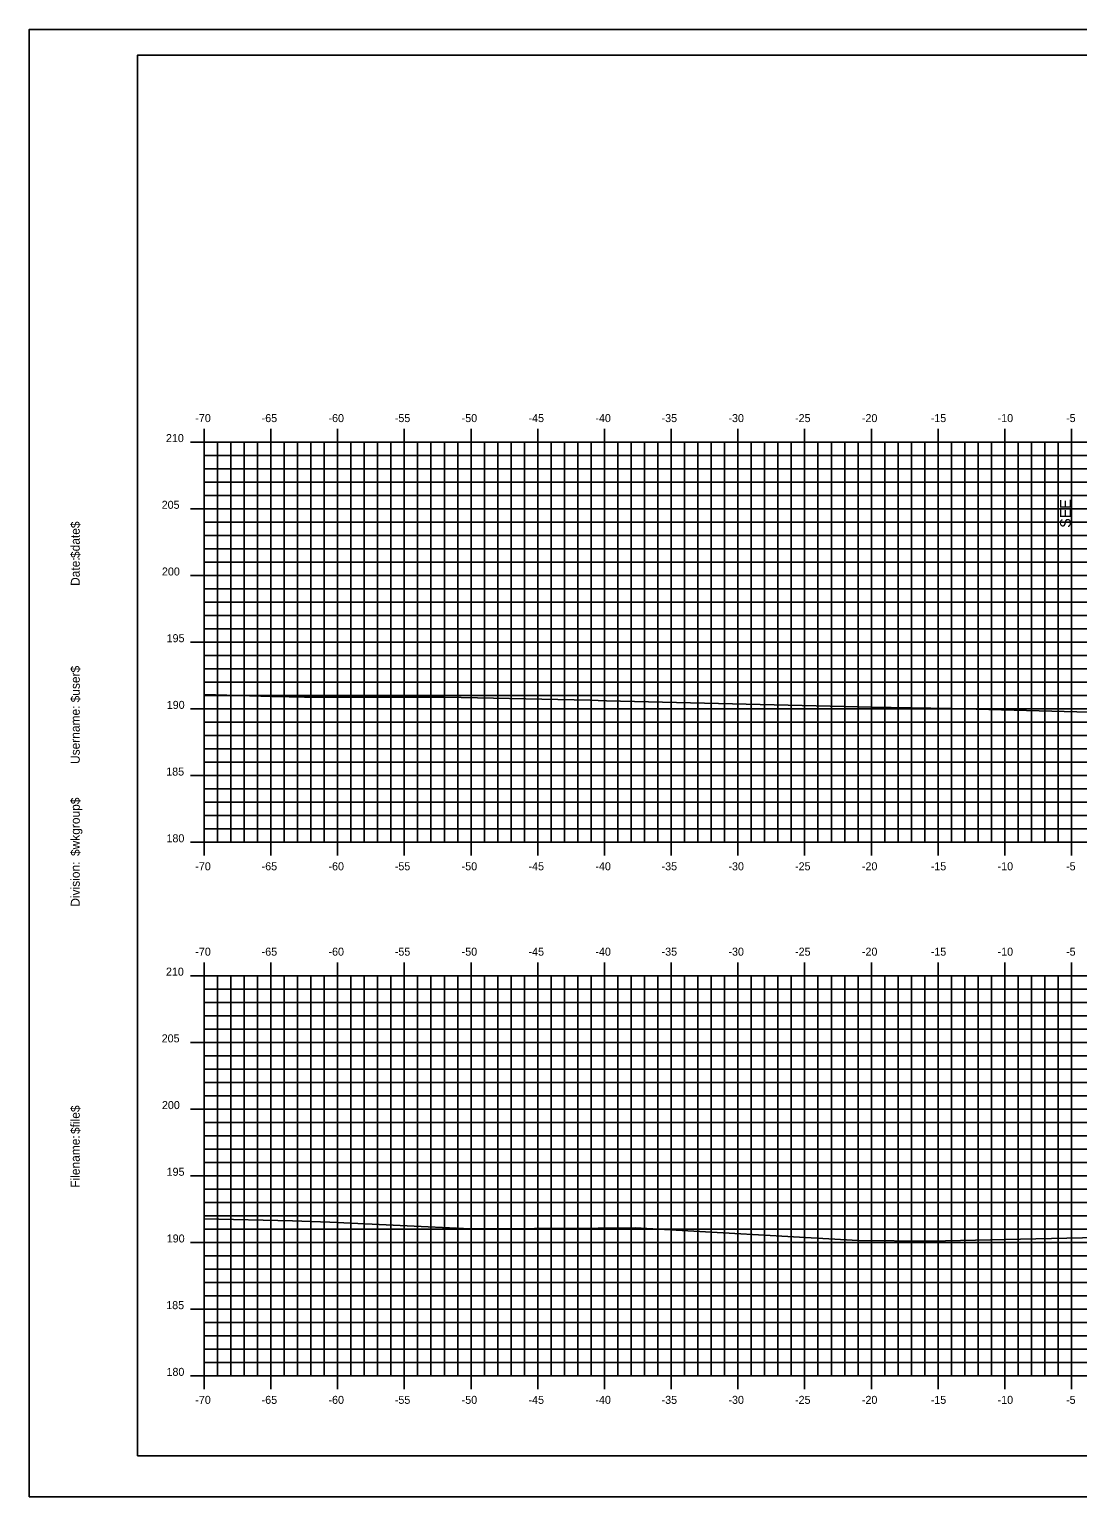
# Model space of a CAD drawing. Extents: x 1723074 to 1723246, y 459560 to 459670.
# Drawn here: x 1723074.4 to 1723152.9, y 459559.6 to 459669.6 of the extents above; entities that cross this region are included whole.
import ezdxf

# ---------------------------------------------------------------- set-up
doc = ezdxf.new("R2010")
doc.units = 0
for name, color, linetype in [('ANNOTATION', 7, 'Continuous'), ('BORDER', 7, 'Continuous'), ('H_V ANNOTATION', 7, 'Continuous'), ('MAJOR', 7, 'Continuous'), ('MINOR', 7, 'Continuous'), ('PLOT BOUNDARY', 7, 'Continuous'), ('S_Roadway_Centerline', 7, 'Continuous')]:
    doc.layers.add(name, color=color, linetype=linetype)

msp = doc.modelspace()

# ---------------------------------------------------------------- linework, layer by layer
at = {"layer": 'BORDER'}
msp.add_lwpolyline([(1723082.45, 459562.61), (1723242.45, 459562.61), (1723242.45, 459667.61), (1723082.45, 459667.61)], close=True, dxfattribs=at)
at = {"layer": 'MAJOR'}
for p, q in [((1723087.45, 459639.61), (1723087.45, 459638.61)), ((1723092.45, 459639.61), (1723092.45, 459638.61)), ((1723097.45, 459639.61), (1723097.45, 459638.61)), ((1723102.45, 459639.61), (1723102.45, 459638.61)), ((1723107.45, 459639.61), (1723107.45, 459638.61)), ((1723112.45, 459639.61), (1723112.45, 459638.61)), ((1723117.45, 459639.61), (1723117.45, 459638.61)), ((1723122.45, 459639.61), (1723122.45, 459638.61)), ((1723127.45, 459639.61), (1723127.45, 459638.61)), ((1723132.45, 459639.61), (1723132.45, 459638.61)), ((1723137.45, 459639.61), (1723137.45, 459638.61)), ((1723142.45, 459639.61), (1723142.45, 459638.61)), ((1723147.45, 459639.61), (1723147.45, 459638.61)), ((1723152.45, 459639.61), (1723152.45, 459638.61)), ((1723086.44, 459638.61), (1723087.45, 459638.61)), ((1723087.45, 459638.61), (1723227.45, 459638.61)), ((1723087.45, 459608.61), (1723087.45, 459638.61)), ((1723087.45, 459608.61), (1723087.45, 459638.61)), ((1723087.45, 459638.61), (1723227.45, 459638.61)), ((1723092.45, 459608.61), (1723092.45, 459638.61)), ((1723097.45, 459608.61), (1723097.45, 459638.61)), ((1723102.45, 459608.61), (1723102.45, 459638.61)), ((1723107.45, 459608.61), (1723107.45, 459638.61)), ((1723112.45, 459608.61), (1723112.45, 459638.61)), ((1723117.45, 459608.61), (1723117.45, 459638.61)), ((1723122.45, 459608.61), (1723122.45, 459638.61)), ((1723127.45, 459608.61), (1723127.45, 459638.61)), ((1723132.45, 459608.61), (1723132.45, 459638.61)), ((1723137.45, 459608.61), (1723137.45, 459638.61)), ((1723142.45, 459608.61), (1723142.45, 459638.61)), ((1723147.45, 459608.61), (1723147.45, 459638.61)), ((1723152.45, 459608.61), (1723152.45, 459638.61)), ((1723086.44, 459633.61), (1723087.45, 459633.61)), ((1723087.45, 459633.61), (1723227.45, 459633.61)), ((1723086.44, 459628.61), (1723087.45, 459628.61)), ((1723087.45, 459628.61), (1723227.45, 459628.61)), ((1723086.44, 459623.61), (1723087.45, 459623.61)), ((1723087.45, 459623.61), (1723227.45, 459623.61)), ((1723086.44, 459618.61), (1723087.45, 459618.61)), ((1723087.45, 459618.61), (1723227.45, 459618.61)), ((1723086.44, 459613.61), (1723087.45, 459613.61)), ((1723087.45, 459613.61), (1723227.45, 459613.61)), ((1723086.44, 459608.61), (1723087.45, 459608.61)), ((1723087.45, 459608.61), (1723227.45, 459608.61)), ((1723087.45, 459608.61), (1723227.45, 459608.61)), ((1723087.45, 459607.61), (1723087.45, 459608.61)), ((1723092.45, 459607.61), (1723092.45, 459608.61)), ((1723097.45, 459607.61), (1723097.45, 459608.61)), ((1723102.45, 459607.61), (1723102.45, 459608.61)), ((1723107.45, 459607.61), (1723107.45, 459608.61)), ((1723112.45, 459607.61), (1723112.45, 459608.61)), ((1723117.45, 459607.61), (1723117.45, 459608.61)), ((1723122.45, 459607.61), (1723122.45, 459608.61)), ((1723127.45, 459607.61), (1723127.45, 459608.61)), ((1723132.45, 459607.61), (1723132.45, 459608.61)), ((1723137.45, 459607.61), (1723137.45, 459608.61)), ((1723142.45, 459607.61), (1723142.45, 459608.61)), ((1723147.45, 459607.61), (1723147.45, 459608.61)), ((1723152.45, 459607.61), (1723152.45, 459608.61)), ((1723087.45, 459599.61), (1723087.45, 459598.61)), ((1723092.45, 459599.61), (1723092.45, 459598.61)), ((1723097.45, 459599.61), (1723097.45, 459598.61)), ((1723102.45, 459599.61), (1723102.45, 459598.61)), ((1723107.45, 459599.61), (1723107.45, 459598.61)), ((1723112.45, 459599.61), (1723112.45, 459598.61)), ((1723117.45, 459599.61), (1723117.45, 459598.61)), ((1723122.45, 459599.61), (1723122.45, 459598.61)), ((1723127.45, 459599.61), (1723127.45, 459598.61)), ((1723132.45, 459599.61), (1723132.45, 459598.61)), ((1723137.45, 459599.61), (1723137.45, 459598.61)), ((1723142.45, 459599.61), (1723142.45, 459598.61)), ((1723147.45, 459599.61), (1723147.45, 459598.61)), ((1723152.45, 459599.61), (1723152.45, 459598.61)), ((1723086.44, 459598.61), (1723087.45, 459598.61)), ((1723087.45, 459598.61), (1723227.45, 459598.61)), ((1723087.45, 459568.61), (1723087.45, 459598.61)), ((1723087.45, 459568.61), (1723087.45, 459598.61)), ((1723087.45, 459598.61), (1723227.45, 459598.61)), ((1723092.45, 459568.61), (1723092.45, 459598.61)), ((1723097.45, 459568.61), (1723097.45, 459598.61)), ((1723102.45, 459568.61), (1723102.45, 459598.61)), ((1723107.45, 459568.61), (1723107.45, 459598.61)), ((1723112.45, 459568.61), (1723112.45, 459598.61)), ((1723117.45, 459568.61), (1723117.45, 459598.61)), ((1723122.45, 459568.61), (1723122.45, 459598.61)), ((1723127.45, 459568.61), (1723127.45, 459598.61)), ((1723132.45, 459568.61), (1723132.45, 459598.61)), ((1723137.45, 459568.61), (1723137.45, 459598.61)), ((1723142.45, 459568.61), (1723142.45, 459598.61)), ((1723147.45, 459568.61), (1723147.45, 459598.61)), ((1723152.45, 459568.61), (1723152.45, 459598.61)), ((1723086.44, 459593.61), (1723087.45, 459593.61)), ((1723087.45, 459593.61), (1723227.45, 459593.61)), ((1723086.44, 459588.61), (1723087.45, 459588.61)), ((1723087.45, 459588.61), (1723227.45, 459588.61)), ((1723086.44, 459583.61), (1723087.45, 459583.61)), ((1723087.45, 459583.61), (1723227.45, 459583.61)), ((1723086.44, 459578.61), (1723087.45, 459578.61)), ((1723087.45, 459578.61), (1723227.45, 459578.61)), ((1723086.44, 459573.61), (1723087.45, 459573.61)), ((1723087.45, 459573.61), (1723227.45, 459573.61)), ((1723086.44, 459568.61), (1723087.45, 459568.61)), ((1723087.45, 459568.61), (1723227.45, 459568.61)), ((1723087.45, 459568.61), (1723227.45, 459568.61)), ((1723087.45, 459567.61), (1723087.45, 459568.61)), ((1723092.45, 459567.61), (1723092.45, 459568.61)), ((1723097.45, 459567.61), (1723097.45, 459568.61)), ((1723102.45, 459567.61), (1723102.45, 459568.61)), ((1723107.45, 459567.61), (1723107.45, 459568.61)), ((1723112.45, 459567.61), (1723112.45, 459568.61)), ((1723117.45, 459567.61), (1723117.45, 459568.61)), ((1723122.45, 459567.61), (1723122.45, 459568.61)), ((1723127.45, 459567.61), (1723127.45, 459568.61)), ((1723132.45, 459567.61), (1723132.45, 459568.61)), ((1723137.45, 459567.61), (1723137.45, 459568.61)), ((1723142.45, 459567.61), (1723142.45, 459568.61)), ((1723147.45, 459567.61), (1723147.45, 459568.61)), ((1723152.45, 459567.61), (1723152.45, 459568.61))]:
    msp.add_line(p, q, dxfattribs=at)
at = {"layer": 'MINOR'}
for p, q in [((1723088.45, 459608.61), (1723088.45, 459638.61)), ((1723089.45, 459608.61), (1723089.45, 459638.61)), ((1723090.45, 459608.61), (1723090.45, 459638.61)), ((1723091.45, 459608.61), (1723091.45, 459638.61)), ((1723093.45, 459608.61), (1723093.45, 459638.61)), ((1723094.45, 459608.61), (1723094.45, 459638.61)), ((1723095.45, 459608.61), (1723095.45, 459638.61)), ((1723096.45, 459608.61), (1723096.45, 459638.61)), ((1723098.45, 459608.61), (1723098.45, 459638.61)), ((1723099.45, 459608.61), (1723099.45, 459638.61)), ((1723100.45, 459608.61), (1723100.45, 459638.61)), ((1723101.45, 459608.61), (1723101.45, 459638.61)), ((1723103.45, 459608.61), (1723103.45, 459638.61)), ((1723104.45, 459608.61), (1723104.45, 459638.61)), ((1723105.45, 459608.61), (1723105.45, 459638.61)), ((1723106.45, 459608.61), (1723106.45, 459638.61)), ((1723108.45, 459608.61), (1723108.45, 459638.61)), ((1723109.45, 459608.61), (1723109.45, 459638.61)), ((1723110.45, 459608.61), (1723110.45, 459638.61)), ((1723111.45, 459608.61), (1723111.45, 459638.61)), ((1723113.45, 459608.61), (1723113.45, 459638.61)), ((1723114.45, 459608.61), (1723114.45, 459638.61)), ((1723115.45, 459608.61), (1723115.45, 459638.61)), ((1723116.45, 459608.61), (1723116.45, 459638.61)), ((1723118.45, 459608.61), (1723118.45, 459638.61)), ((1723119.45, 459608.61), (1723119.45, 459638.61)), ((1723120.45, 459608.61), (1723120.45, 459638.61)), ((1723121.45, 459608.61), (1723121.45, 459638.61)), ((1723123.45, 459608.61), (1723123.45, 459638.61)), ((1723124.45, 459608.61), (1723124.45, 459638.61)), ((1723125.45, 459608.61), (1723125.45, 459638.61)), ((1723126.45, 459608.61), (1723126.45, 459638.61)), ((1723128.45, 459608.61), (1723128.45, 459638.61)), ((1723129.45, 459608.61), (1723129.45, 459638.61)), ((1723130.45, 459608.61), (1723130.45, 459638.61)), ((1723131.45, 459608.61), (1723131.45, 459638.61)), ((1723133.45, 459608.61), (1723133.45, 459638.61)), ((1723134.45, 459608.61), (1723134.45, 459638.61)), ((1723135.45, 459608.61), (1723135.45, 459638.61)), ((1723136.45, 459608.61), (1723136.45, 459638.61)), ((1723138.45, 459608.61), (1723138.45, 459638.61)), ((1723139.45, 459608.61), (1723139.45, 459638.61)), ((1723140.45, 459608.61), (1723140.45, 459638.61)), ((1723141.45, 459608.61), (1723141.45, 459638.61)), ((1723143.45, 459608.61), (1723143.45, 459638.61)), ((1723144.45, 459608.61), (1723144.45, 459638.61)), ((1723145.45, 459608.61), (1723145.45, 459638.61)), ((1723146.45, 459608.61), (1723146.45, 459638.61)), ((1723148.45, 459608.61), (1723148.45, 459638.61)), ((1723149.45, 459608.61), (1723149.45, 459638.61)), ((1723150.45, 459608.61), (1723150.45, 459638.61)), ((1723151.45, 459608.61), (1723151.45, 459638.61)), ((1723087.45, 459637.61), (1723227.45, 459637.61)), ((1723087.45, 459637.61), (1723088.45, 459637.61)), ((1723087.45, 459636.61), (1723227.45, 459636.61)), ((1723087.45, 459636.61), (1723088.45, 459636.61)), ((1723087.45, 459635.61), (1723227.45, 459635.61)), ((1723087.45, 459635.61), (1723088.45, 459635.61)), ((1723087.45, 459634.61), (1723227.45, 459634.61)), ((1723087.45, 459634.61), (1723088.45, 459634.61)), ((1723087.45, 459632.61), (1723227.45, 459632.61)), ((1723087.45, 459632.61), (1723088.45, 459632.61)), ((1723087.45, 459631.61), (1723227.45, 459631.61)), ((1723087.45, 459631.61), (1723088.45, 459631.61)), ((1723087.45, 459630.61), (1723227.45, 459630.61)), ((1723087.45, 459630.61), (1723088.45, 459630.61)), ((1723087.45, 459629.61), (1723227.45, 459629.61)), ((1723087.45, 459629.61), (1723088.45, 459629.61)), ((1723087.45, 459627.61), (1723227.45, 459627.61)), ((1723087.45, 459627.61), (1723088.45, 459627.61)), ((1723087.45, 459626.61), (1723227.45, 459626.61)), ((1723087.45, 459626.61), (1723088.45, 459626.61)), ((1723087.45, 459625.61), (1723227.45, 459625.61)), ((1723087.45, 459625.61), (1723088.45, 459625.61)), ((1723087.45, 459624.61), (1723227.45, 459624.61)), ((1723087.45, 459624.61), (1723088.45, 459624.61)), ((1723087.45, 459622.61), (1723227.45, 459622.61)), ((1723087.45, 459622.61), (1723088.45, 459622.61)), ((1723087.45, 459621.61), (1723227.45, 459621.61)), ((1723087.45, 459621.61), (1723088.45, 459621.61)), ((1723087.45, 459620.61), (1723227.45, 459620.61)), ((1723087.45, 459620.61), (1723088.45, 459620.61)), ((1723087.45, 459619.61), (1723227.45, 459619.61)), ((1723087.45, 459619.61), (1723088.45, 459619.61)), ((1723087.45, 459617.61), (1723227.45, 459617.61)), ((1723087.45, 459617.61), (1723088.45, 459617.61)), ((1723087.45, 459616.61), (1723227.45, 459616.61)), ((1723087.45, 459616.61), (1723088.45, 459616.61)), ((1723087.45, 459615.61), (1723227.45, 459615.61)), ((1723087.45, 459615.61), (1723088.45, 459615.61)), ((1723087.45, 459614.61), (1723227.45, 459614.61)), ((1723087.45, 459614.61), (1723088.45, 459614.61)), ((1723087.45, 459612.61), (1723227.45, 459612.61)), ((1723087.45, 459612.61), (1723088.45, 459612.61)), ((1723087.45, 459611.61), (1723227.45, 459611.61)), ((1723087.45, 459611.61), (1723088.45, 459611.61)), ((1723087.45, 459610.61), (1723227.45, 459610.61)), ((1723087.45, 459610.61), (1723088.45, 459610.61)), ((1723087.45, 459609.61), (1723227.45, 459609.61)), ((1723087.45, 459609.61), (1723088.45, 459609.61)), ((1723087.45, 459597.61), (1723227.45, 459597.61)), ((1723087.45, 459597.61), (1723088.45, 459597.61)), ((1723088.45, 459568.61), (1723088.45, 459598.61)), ((1723089.45, 459568.61), (1723089.45, 459598.61)), ((1723090.45, 459568.61), (1723090.45, 459598.61)), ((1723091.45, 459568.61), (1723091.45, 459598.61)), ((1723093.45, 459568.61), (1723093.45, 459598.61)), ((1723094.45, 459568.61), (1723094.45, 459598.61)), ((1723095.45, 459568.61), (1723095.45, 459598.61)), ((1723096.45, 459568.61), (1723096.45, 459598.61)), ((1723098.45, 459568.61), (1723098.45, 459598.61)), ((1723099.45, 459568.61), (1723099.45, 459598.61)), ((1723100.45, 459568.61), (1723100.45, 459598.61)), ((1723101.45, 459568.61), (1723101.45, 459598.61)), ((1723103.45, 459568.61), (1723103.45, 459598.61)), ((1723104.45, 459568.61), (1723104.45, 459598.61)), ((1723105.45, 459568.61), (1723105.45, 459598.61)), ((1723106.45, 459568.61), (1723106.45, 459598.61)), ((1723108.45, 459568.61), (1723108.45, 459598.61)), ((1723109.45, 459568.61), (1723109.45, 459598.61)), ((1723110.45, 459568.61), (1723110.45, 459598.61)), ((1723111.45, 459568.61), (1723111.45, 459598.61)), ((1723113.45, 459568.61), (1723113.45, 459598.61)), ((1723114.45, 459568.61), (1723114.45, 459598.61)), ((1723115.45, 459568.61), (1723115.45, 459598.61)), ((1723116.45, 459568.61), (1723116.45, 459598.61)), ((1723118.45, 459568.61), (1723118.45, 459598.61)), ((1723119.45, 459568.61), (1723119.45, 459598.61)), ((1723120.45, 459568.61), (1723120.45, 459598.61)), ((1723121.45, 459568.61), (1723121.45, 459598.61)), ((1723123.45, 459568.61), (1723123.45, 459598.61)), ((1723124.45, 459568.61), (1723124.45, 459598.61)), ((1723125.45, 459568.61), (1723125.45, 459598.61)), ((1723126.45, 459568.61), (1723126.45, 459598.61)), ((1723128.45, 459568.61), (1723128.45, 459598.61)), ((1723129.45, 459568.61), (1723129.45, 459598.61)), ((1723130.45, 459568.61), (1723130.45, 459598.61)), ((1723131.45, 459568.61), (1723131.45, 459598.61)), ((1723133.45, 459568.61), (1723133.45, 459598.61)), ((1723134.45, 459568.61), (1723134.45, 459598.61)), ((1723135.45, 459568.61), (1723135.45, 459598.61)), ((1723136.45, 459568.61), (1723136.45, 459598.61)), ((1723138.45, 459568.61), (1723138.45, 459598.61)), ((1723139.45, 459568.61), (1723139.45, 459598.61)), ((1723140.45, 459568.61), (1723140.45, 459598.61)), ((1723141.45, 459568.61), (1723141.45, 459598.61)), ((1723143.45, 459568.61), (1723143.45, 459598.61)), ((1723144.45, 459568.61), (1723144.45, 459598.61)), ((1723145.45, 459568.61), (1723145.45, 459598.61)), ((1723146.45, 459568.61), (1723146.45, 459598.61)), ((1723148.45, 459568.61), (1723148.45, 459598.61)), ((1723149.45, 459568.61), (1723149.45, 459598.61)), ((1723150.45, 459568.61), (1723150.45, 459598.61)), ((1723151.45, 459568.61), (1723151.45, 459598.61)), ((1723087.45, 459596.61), (1723227.45, 459596.61)), ((1723087.45, 459596.61), (1723088.45, 459596.61)), ((1723087.45, 459595.61), (1723227.45, 459595.61)), ((1723087.45, 459595.61), (1723088.45, 459595.61)), ((1723087.45, 459594.61), (1723227.45, 459594.61)), ((1723087.45, 459594.61), (1723088.45, 459594.61)), ((1723087.45, 459592.61), (1723227.45, 459592.61)), ((1723087.45, 459592.61), (1723088.45, 459592.61)), ((1723087.45, 459591.61), (1723227.45, 459591.61)), ((1723087.45, 459591.61), (1723088.45, 459591.61)), ((1723087.45, 459590.61), (1723227.45, 459590.61)), ((1723087.45, 459590.61), (1723088.45, 459590.61)), ((1723087.45, 459589.61), (1723227.45, 459589.61)), ((1723087.45, 459589.61), (1723088.45, 459589.61)), ((1723087.45, 459587.61), (1723227.45, 459587.61)), ((1723087.45, 459587.61), (1723088.45, 459587.61)), ((1723087.45, 459586.61), (1723227.45, 459586.61)), ((1723087.45, 459586.61), (1723088.45, 459586.61)), ((1723087.45, 459585.61), (1723227.45, 459585.61)), ((1723087.45, 459585.61), (1723088.45, 459585.61)), ((1723087.45, 459584.61), (1723227.45, 459584.61)), ((1723087.45, 459584.61), (1723088.45, 459584.61)), ((1723087.45, 459582.61), (1723227.45, 459582.61)), ((1723087.45, 459582.61), (1723088.45, 459582.61)), ((1723087.45, 459581.61), (1723227.45, 459581.61)), ((1723087.45, 459581.61), (1723088.45, 459581.61)), ((1723087.45, 459580.61), (1723227.45, 459580.61)), ((1723087.45, 459580.61), (1723088.45, 459580.61)), ((1723087.45, 459579.61), (1723227.45, 459579.61)), ((1723087.45, 459579.61), (1723088.45, 459579.61)), ((1723087.45, 459577.61), (1723227.45, 459577.61)), ((1723087.45, 459577.61), (1723088.45, 459577.61)), ((1723087.45, 459576.61), (1723227.45, 459576.61)), ((1723087.45, 459576.61), (1723088.45, 459576.61)), ((1723087.45, 459575.61), (1723227.45, 459575.61)), ((1723087.45, 459575.61), (1723088.45, 459575.61)), ((1723087.45, 459574.61), (1723227.45, 459574.61)), ((1723087.45, 459574.61), (1723088.45, 459574.61)), ((1723087.45, 459572.61), (1723227.45, 459572.61)), ((1723087.45, 459572.61), (1723088.45, 459572.61)), ((1723087.45, 459571.61), (1723227.45, 459571.61)), ((1723087.45, 459571.61), (1723088.45, 459571.61)), ((1723087.45, 459570.61), (1723227.45, 459570.61)), ((1723087.45, 459570.61), (1723088.45, 459570.61)), ((1723087.45, 459569.61), (1723227.45, 459569.61)), ((1723087.45, 459569.61), (1723088.45, 459569.61))]:
    msp.add_line(p, q, dxfattribs=at)
at = {"layer": 'PLOT BOUNDARY'}
msp.add_lwpolyline([(1723074.35, 459559.55), (1723244.35, 459559.55), (1723244.35, 459669.55), (1723074.35, 459669.55)], close=True, dxfattribs=at)
at = {"layer": 'S_Roadway_Centerline'}
for points in [[(1723087.45, 459619.7), (1723092.56, 459619.55), (1723093.81, 459619.52), (1723094.98, 459619.48), (1723105.51, 459619.49), (1723116.37, 459619.26), (1723116.98, 459619.24), (1723117.59, 459619.21), (1723137.52, 459618.75), (1723140.37, 459618.69), (1723143.42, 459618.64), (1723159.43, 459618.21), (1723168.45, 459618.03), (1723174.35, 459617.95), (1723180.25, 459617.81), (1723187.85, 459617.71), (1723193.55, 459617.67), (1723203.23, 459617.61), (1723209.86, 459617.48), (1723219.82, 459617.19), (1723224.45, 459617.09), (1723227.45, 459617.14)], [(1723087.45, 459580.37), (1723094.07, 459580.23), (1723096.87, 459580.13), (1723107.41, 459579.62), (1723116.97, 459579.67), (1723119.74, 459579.7), (1723136.46, 459578.75), (1723141.89, 459578.71), (1723148.62, 459578.86), (1723154.42, 459578.97), (1723159.3, 459578.81), (1723165.41, 459578.6), (1723173.15, 459578.49), (1723177.65, 459578.45), (1723182.29, 459578.32), (1723189.49, 459578.19), (1723198.21, 459577.98), (1723203.59, 459577.89), (1723221.84, 459577.68), (1723222.68, 459577.68), (1723223.44, 459577.69), (1723227.45, 459577.7)]]:
    msp.add_lwpolyline(points, dxfattribs=at)

# ---------------------------------------------------------------- texts
at = {"layer": 'ANNOTATION'}
msp.add_text('SEE', height=0.8, rotation=90, dxfattribs=at).set_placement((1723152.39, 459632.19))
at = {"layer": 'BORDER'}
for s, p in [('$date$', (1723078.13, 459629.92)), ('Date:', (1723078.13, 459627.83)), ('$user$', (1723078.13, 459619.1)), ('Username:', (1723078.13, 459614.48)), ('$wkgroup$', (1723078.13, 459607.58)), ('Division:', (1723078.13, 459603.78)), ('$file$', (1723078.13, 459586.74)), ('Filename:', (1723078.13, 459582.71))]:
    msp.add_text(s, height=0.67, rotation=90, dxfattribs=at).set_placement(p)
at = {"layer": 'H_V ANNOTATION'}
for s, p in [('-70', (1723086.79, 459640.11)), ('-65', (1723091.76, 459640.11)), ('-60', (1723096.77, 459640.11)), ('-55', (1723101.74, 459640.11)), ('-50', (1723106.75, 459640.11)), ('-45', (1723111.76, 459640.11)), ('-40', (1723116.77, 459640.11)), ('-35', (1723121.73, 459640.11)), ('-30', (1723126.74, 459640.11)), ('-25', (1723131.73, 459640.11)), ('-20', (1723136.74, 459640.11)), ('-15', (1723141.9, 459640.11)), ('-10', (1723146.91, 459640.11)), ('-5', (1723152.04, 459640.11)), ('210', (1723084.59, 459638.61)), ('205', (1723084.27, 459633.61)), ('200', (1723084.29, 459628.61)), ('195', (1723084.64, 459623.61)), ('190', (1723084.65, 459618.61)), ('185', (1723084.61, 459613.61)), ('180', (1723084.63, 459608.61)), ('-70', (1723086.79, 459606.51)), ('-65', (1723091.76, 459606.51)), ('-60', (1723096.77, 459606.51)), ('-55', (1723101.74, 459606.51)), ('-50', (1723106.75, 459606.51)), ('-45', (1723111.76, 459606.51)), ('-40', (1723116.77, 459606.51)), ('-35', (1723121.73, 459606.51)), ('-30', (1723126.74, 459606.51)), ('-25', (1723131.73, 459606.51)), ('-20', (1723136.74, 459606.51)), ('-15', (1723141.9, 459606.51)), ('-10', (1723146.91, 459606.51)), ('-5', (1723152.04, 459606.51)), ('-70', (1723086.79, 459600.11)), ('-65', (1723091.76, 459600.11)), ('-60', (1723096.77, 459600.11)), ('-55', (1723101.74, 459600.11)), ('-50', (1723106.75, 459600.11)), ('-45', (1723111.76, 459600.11)), ('-40', (1723116.77, 459600.11)), ('-35', (1723121.73, 459600.11)), ('-30', (1723126.74, 459600.11)), ('-25', (1723131.73, 459600.11)), ('-20', (1723136.74, 459600.11)), ('-15', (1723141.9, 459600.11)), ('-10', (1723146.91, 459600.11)), ('-5', (1723152.04, 459600.11)), ('210', (1723084.59, 459598.61)), ('205', (1723084.27, 459593.61)), ('200', (1723084.29, 459588.61)), ('195', (1723084.64, 459583.61)), ('190', (1723084.65, 459578.61)), ('185', (1723084.61, 459573.61)), ('180', (1723084.63, 459568.61)), ('-70', (1723086.79, 459566.51)), ('-65', (1723091.76, 459566.51)), ('-60', (1723096.77, 459566.51)), ('-55', (1723101.74, 459566.51)), ('-50', (1723106.75, 459566.51)), ('-45', (1723111.76, 459566.51)), ('-40', (1723116.77, 459566.51)), ('-35', (1723121.73, 459566.51)), ('-30', (1723126.74, 459566.51)), ('-25', (1723131.73, 459566.51)), ('-20', (1723136.74, 459566.51)), ('-15', (1723141.9, 459566.51)), ('-10', (1723146.91, 459566.51)), ('-5', (1723152.04, 459566.51))]:
    msp.add_text(s, height=0.6, dxfattribs=at).set_placement(p)
at = {"layer": 'MAJOR'}
for p in [(1723087.44, 459608.61), (1723087.44, 459568.61)]:
    msp.add_text('-', height=0.006, dxfattribs=at).set_placement(p)

doc.saveas('drawing.dxf')
